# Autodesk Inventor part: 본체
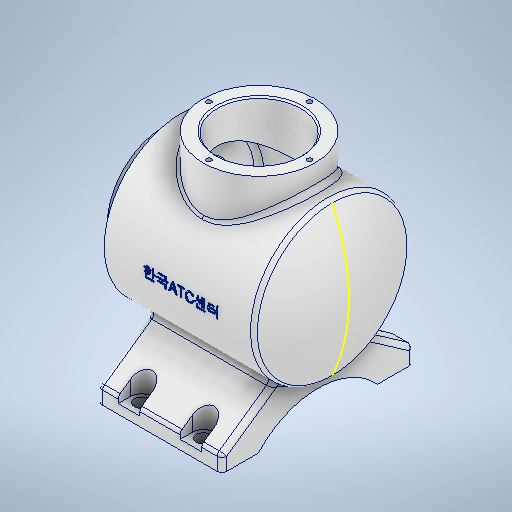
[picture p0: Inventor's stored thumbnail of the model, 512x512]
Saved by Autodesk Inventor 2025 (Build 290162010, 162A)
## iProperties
Created: 2024-07
Part Number: 본체
Material: 알루미늄 6061
Document SubType Name: Modeling
Designer: Admin
Density: 2.7 g/cm^3
Appearance: 알루미늄 - 평지
Mass: 1332.66 g
Surface Area: 1062.33 cm^2
Volume: 493.576 cm^3
Author: Admin
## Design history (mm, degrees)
sketch "스케치1"
  geometry: L1 (-47, 0)-(65, 0); L2 (0, 50)-(96.336, 50); L3 (96.336, 50)-(96.336, 0); L4 (96.336, 0)-(0, 0); L5 (0, 0)-(0, 50); L6 (108, 0)-(0, 0); L7 (108, 0)-(0, 0); A1 r 113 centre (-5, 0) between (108, 0) and (96.336, 50); 5 further points
  constraints: 14 end point, 2 horizontal, 2 parallel, 2 point on circle, 1 centre point, 1 coincident, 1 collinear, 1 perpendicular
  dimensions: "d7" = 108 distance of L6.start point (0, 0); "d9" = 50 distance of L4.end L2.start; "d108" = 113 radius of A1
revolve "회전1" sketch "스케치1" stored, may be unused: angle "d10" = 90 deg
fillet "모깎기1" dims "d11" = 3
sketch "스케치2"
  geometry: L1 (0, 0)-(0, -77); C1 r 36 at (0, 0)
  constraints: 2 end point, 1 centre point, 1 coincident, 1 vertical
  dimensions: "d12" = 77 distance of L1.start L1.end; "d13" = 72 diameter of C1
node "작업 평면3"
feature "쉘4" dims "d53" = 7
extrude "돌출2" join sketch "스케치2" distance "d29" = 12; taper "d30" = 0 deg
sketch "스케치5"
  geometry: L1 (97.166, 48.282)-(97.166, -48.282) reference; A1 r 113 centre (-5, 0) between (97.166, -48.282) and (97.166, 48.282) reference; 1 further point
  node "투영된 루프1"
node "작업 평면4"
sketch "스케치6"
  geometry: L1 (12, -36)-(12, 36) reference; L2 (12, 0)-(-50, 0); C1 r 36 at (-50, 0); 1 further point
  constraints: 2 end point, 1 centre point, 1 coincident, 1 horizontal, 1 midpoint
  dimensions: "d32" = 62 distance of L2.start L2.end; "d33" = 72 diameter of C1
extrude "돌출3" join sketch "스케치6" stored distance "d34" = 12; taper "d35" = 0 deg; dims "d36" = 54
sketch "스케치7"
  geometry: C1 r 36 at (0, 0) reference; C2 r 27 at (0, 0); 1 further point
  constraints: 1 centre point, 1 coincident
  dimensions: "d36" = 54 diameter of C2
extrude "돌출4" cut sketch "스케치7" distance "d37" = 50; taper "d38" = 0 deg
sketch "스케치8"
  geometry: C1 r 27 at (0, 0); 1 further point
  constraints: 1 centre point, 1 coincident
  dimensions: "d39" = 54 diameter of C1
sketch "스케치4"
  geometry: L1 (-42.278, -26.694)-(-67, -62); L2 (-67, -62)-(-77, -62); L3 (-77, -62)-(-77, 62); L4 (-77, 62)-(-67, 62); L5 (-67, 62)-(-42.278, 26.694); L6 (0, 0)-(-77, 0); L7 (-77, 9.118)-(-77, 34.784); L8 (-77, -38.5)-(-77, 38.5); L9 (-77, -62)-(-77, 62); A1 r 50 centre (0, 0) between (-42.278, -26.694) and (-42.278, 26.694); A2 r 52.096 centre (-112.096, 0) between (-77, -38.5) and (-77, 38.5); 8 further points
  constraints: 18 end point, 5 midpoint, 5 point on circle, 3 coincident, 2 centre point, 2 perpendicular, 2 point on line, 1 collinear, 1 horizontal, 1 vertical, 2 other
  dimensions: "d22" = 55 deg angle of L4 L5; "d24" = 77 distance of L8.start L8.end; "d25" = 17 distance from line of L3 point (-60, 0); "d26" = 100 diameter of A1; "d82" = 77 distance from line of L9 point (0, 0); "d98" = 124 distance of point (-72, -62) point (-72, 62); "d107" = 10 distance of L3.end L4.end
extrude "돌출1" join sketch "스케치4" distance "d27" = 80; taper "d28" = 0 deg
extrude "돌출5" cut sketch "스케치8" distance "d45" = 50; taper "d46" = 0 deg
chamfer "모따기1" distance "d54" = 1; stored, may be unused: second distance "d55" = 2, angle "d56" = 45 deg
fillet "모깎기2" dims "d57" = 3
sketch "스케치10" dims "d58" = 65
  geometry: L1 (0, 0)-(0, 32.5); 1 further point
  constraints: 2 end point, 1 coincident, 1 vertical, 1 vertical alignment, 2 other
sketch "스케치11" dims "d59" = 65
  geometry: L1 (0, 0)-(32.5, 0); C1 r 36 at (0, 0) reference; 1 further point
  constraints: 2 end point, 1 coincident, 1 horizontal alignment, 2 other
hole "구멍1" sketch "스케치11" at (32.5, 0) diameter "d60" = 3.242; stored, may be unused: countersink angle "d64" = 90 deg, drill point angle "d66" = 120 deg; dims "d61" = 8, "d62" = 4, "d63" = 2, "d65" = 10
hole "구멍2" sketch "스케치10" diameter "d67" = 3.242; stored, may be unused: countersink angle "d71" = 90 deg, drill point angle "d73" = 120 deg; dims "d68" = 8, "d69" = 4, "d70" = 2, "d72" = 10
fillet "모깎기3" dims "d80" = 3
sketch "스케치12"
  geometry: 1 further point
sketch "스케치13"
  geometry: 1 further point
node "작업 평면6"
sketch "스케치14"
  geometry: L1 (-8, 62)-(-8, 38.5) reference; L2 (-8, 62)-(-8, 38.5) reference; L3 (-8, 38.5)-(-88, 38.5) reference; L4 (-88, 62)-(-88, 38.5) reference; L5 (-8, 62)-(-88, 62) reference; L6 (-8, 62)-(-28, 62); L7 (-28, 62)-(-68, 62); L8 (-21, 54)-(-35, 54); L9 (-35, 54)-(-35, 62); L10 (-35, 62)-(-21, 62); L11 (-21, 62)-(-21, 54); L12 (-75, 54)-(-61, 54); L13 (-61, 54)-(-61, 62); L14 (-61, 62)-(-75, 62); L15 (-75, 62)-(-75, 54); A1 r 7 centre (-28, 54) between (-35, 54) and (-21, 54); A2 r 7 centre (-68, 54) between (-75, 54) and (-61, 54); 5 further points
  constraints: 20 end point, 5 parallel, 4 midpoint, 4 point on circle, 2 centre point, 2 horizontal, 2 perpendicular, 2 point on line
  dimensions: "d84" = 20 distance of L6.end L2.start; "d85" = 40 distance of L6.end L7.end; "d86" = 14 distance of L8.start L8.end; "d87" = 14 distance of L12.start L12.end; "d88" = 8 distance of L8.end L9.end
  node "투영된 루프2"
extrude "돌출6" cut sketch "스케치14" distance "d89" = 20; taper "d90" = 0 deg
hole "구멍3" sketch "스케치14" diameter "d91" = 9; stored, may be unused: countersink angle "d95" = 90 deg, drill point angle "d97" = 0 deg; dims "d92" = 6, "d93" = 4, "d94" = 2, "d96" = 8
fillet "모깎기4" dims "d99" = 3
fillet "모깎기5" dims "d100" = 3
fillet "모깎기6" dims "d101" = 3
node "작업 평면8"
sketch "스케치16"
  geometry: L1 (0, 0)-(100, 0); L2 (-12, 36)-(-12, -36) reference; 2 further points
  constraints: 2 end point, 1 coincident, 1 horizontal, 1 midpoint, 1 other
  dimensions: "d103" = 62 distance from line of point (50, 0) L2
feature "엠보싱1" sketch "스케치16" dims "d7" = 108, "d9" = 50, "d104" = 0.5, "d105" = 0, "d108" = 113
feature "γ耀ε耀η耀ι耀λ耀ν耀ο耀ρ耀" dims "d7" = 108, "d9" = 50, "d10" = 90 deg, "d11" = 3, "d12" = 77, "d13" = 72, "d21" = 8, "d22" = 55 deg, "d24" = 77, "d25" = 17, "d26" = 100, "d27" = 80, "d28" = 0, "d29" = 12, "d30" = 0, "d31" = 65, "d32" = 62, "d33" = 72, "d34" = 12, "d35" = 0, "d36" = 54, "d37" = 50, "d38" = 0, "d39" = 54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
node "솔리드1"
pattern_circular "원형 패턴1" dims angle "d75" = 360 deg
pattern_circular "원형 패턴2" dims angle "d78" = 360 deg
mirror "미러1"
feature "A9D066F2-1C7D-4E18-AEED-F7BC21143FA4" dims "d91" = 9, "d92" = 6, "d93" = 4, "d94" = 2, "d95" = 90 deg, "d96" = 8, "d97" = 0
